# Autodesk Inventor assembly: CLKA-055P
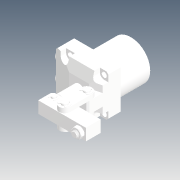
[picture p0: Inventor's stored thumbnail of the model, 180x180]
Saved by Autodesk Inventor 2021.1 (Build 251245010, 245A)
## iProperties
Created: 2019-04
Part Number: CLKA-055P
Description: STEP AP214
Document SubType Name: Assembly
Designer: user
Title: CLKA-055P.STEP
Revision Number: ÈÎºÎ
Sending System: SolidWorks 2016
Preprocessor: SwSTEP 2.0
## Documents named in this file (12)
- D:\Vault_2016\Projekty\Clamptek\Hydraulic\CLKA-P\Inventor\CLKA-055P\CLKA-055P.iam
- D:\Vault_2016\Projekty\Clamptek\Hydraulic\CLKA-P\Inventor\CLKA-055P\CLKA-055P-benti.ipt
- D:\Vault_2016\Projekty\Clamptek\Hydraulic\CLKA-P\Inventor\CLKA-055P\6MM¿ª¿Úµ²È¦.ipt
- D:\Vault_2016\Projekty\Clamptek\Hydraulic\CLKA-P\Inventor\CLKA-055P\8MMdangjuan.ipt
- D:\Vault_2016\Projekty\Clamptek\Hydraulic\CLKA-P\Inventor\CLKA-055P\duanxiao.ipt
- D:\Vault_2016\Projekty\Clamptek\Hydraulic\CLKA-P\Inventor\CLKA-055P\huosaigan.ipt
- D:\Vault_2016\Projekty\Clamptek\Hydraulic\CLKA-P\Inventor\CLKA-055P\liangan.ipt
- D:\Vault_2016\Projekty\Clamptek\Hydraulic\CLKA-P\Inventor\CLKA-055P\luosi.ipt
- D:\Vault_2016\Projekty\Clamptek\Hydraulic\CLKA-P\Inventor\CLKA-055P\M8luomu.ipt
- D:\Vault_2016\Projekty\Clamptek\Hydraulic\CLKA-P\Inventor\CLKA-055P\yabi.ipt
- D:\Vault_2016\Projekty\Clamptek\Hydraulic\CLKA-P\Inventor\CLKA-055P\zhangxiao.ipt
- D:\Vault_2016\Projekty\Clamptek\Hydraulic\CLKA-P\Inventor\CLKA-055P\¶ÂÍ·G8-1.ipt
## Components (18 placed, 18 different names)
1. CLKA-055P-benti_1
2. 6MM¿ª¿Úµ²È¦_2
3. 8MMdangjuan_3
4. duanxiao_4
5. huosaigan_5
6. liangan_6
7. luosi_7
8. M8luomu_8
9. yabi_9
10. zhangxiao_10
11. liangan_11
12. zhangxiao_12
13. 8MMdangjuan_13
14. 8MMdangjuan_14
15. 8MMdangjuan_15
16. 6MM¿ª¿Úµ²È¦_16
17. ¶ÂÍ·G8-1_17
18. ¶ÂÍ·G8-1_18
